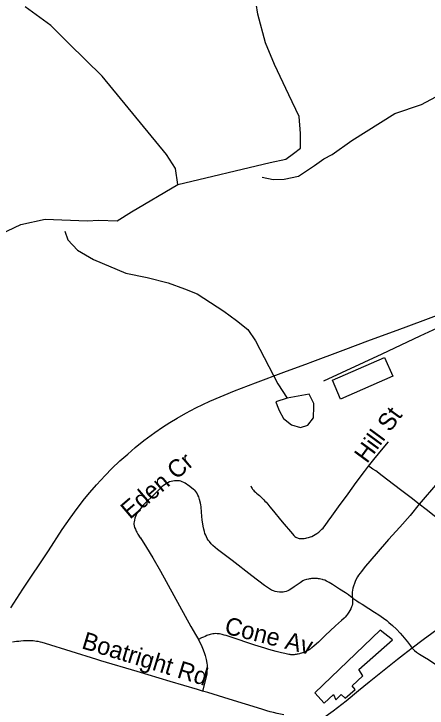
# Model space of a CAD drawing. Extents: x 1383679 to 1536984, y 460658 to 651027.
# Drawn here: x 1430469 to 1432722, y 488802 to 492583 of the extents above; entities that cross this region are included whole.
import ezdxf

# ---------------------------------------------------------------- set-up
doc = ezdxf.new("R2010")
doc.units = 0
for name, color, linetype in [('Exist Cultural Warehouse Building Footprint', 7, 'Continuous'), ('Exist Hydrographic Creek Single Shore', 7, 'Continuous'), ('Exist Hydrographic Misc Water Feature', 7, 'Continuous'), ('Exist Railroad Mainline', 7, 'Continuous'), ('Exist Railroad Spur', 7, 'Continuous'), ('Exist Road Non-System Type 51', 7, 'Continuous'), ('Exist Road Non-System Type 51 Label', 7, 'Continuous')]:
    doc.layers.add(name, color=color, linetype=linetype)

msp = doc.modelspace()

# ---------------------------------------------------------------- linework, layer by layer
at = {"layer": 'Exist Cultural Warehouse Building Footprint'}
for points in [[(1432489.4, 490712.1), (1432534.4, 490609.3), (1432250.4, 490484.9), (1432205.3, 490587.7), (1432489.4, 490712.1)], [(1432465.3, 489227), (1432110.3, 488885), (1432161, 488828.8), (1432211.7, 488875.7), (1432223.8, 488847.6), (1432252.8, 488875.7), (1432274.5, 488856.9), (1432330, 488903.8), (1432313.1, 488922.5), (1432371.1, 488978.7), (1432349.4, 489011.5), (1432532.9, 489173.2), (1432465.3, 489227)]]:
    msp.add_lwpolyline(points, dxfattribs=at)
at = {"layer": 'Exist Hydrographic Creek Single Shore'}
for points in [[(1431363.3, 491653.7), (1431867.1, 491773.5), (1431951.4, 491791.3), (1431993.6, 491822.4), (1432031.3, 491851.2), (1432031.3, 491931.1), (1432024.7, 492024.3), (1431968.2, 492141.9), (1431889.3, 492308.4), (1431841.6, 492426), (1431799.4, 492581.3), (1431762.8, 492816.6), (1431749.5, 492971.9), (1431774.4, 493174.4), (1431871.7, 493357.8), (1432018, 493546.7), (1432202.2, 493801.9), (1432237.7, 493963.9), (1432286.5, 494061.6), (1432324.2, 494168.1), (1432310.9, 494345.6), (1432318.7, 494667.4), (1432283.2, 494800.6), (1432128, 494953)], [(1431363.3, 491653.7), (1431350, 491740.3), (1431301, 491817.6), (1430950.6, 492244), (1430768.6, 492421.6), (1430670.9, 492519.2), (1430531.1, 492621.3)], [(1429661.1, 488410.2), (1429731.2, 488999.7), (1429702.2, 489233.3), (1429714.2, 489443.1), (1430018.5, 490728.3), (1430038.5, 490861.4), (1430062.9, 490923.6), (1430134.3, 490995.2), (1430204.6, 491104.1), (1430250.5, 491197), (1430311.4, 491309.7), (1430395.7, 491383), (1430506.7, 491436.2), (1430639.9, 491465.1), (1430868.4, 491456.2), (1430932.8, 491460.6), (1431032.7, 491456.2), (1431110.3, 491505), (1431363.3, 491653.7)]]:
    msp.add_lwpolyline(points, dxfattribs=at)
at = {"layer": 'Exist Hydrographic Misc Water Feature'}
for points in [[(1431822.6, 491694.3), (1431882.5, 491680.8), (1431942.6, 491683.7), (1432020.9, 491700.1), (1432108, 491756.7), (1432158.8, 491793.4), (1432205.2, 491817.1), (1432310.8, 491892.9), (1432545.8, 492040), (1432690.8, 492089.6), (1432848.5, 492172.6), (1433083.1, 492300), (1433113.3, 492307.5), (1433237.5, 492314.9), (1433352.6, 492366.8), (1433471, 492386.5), (1433557.9, 492430.7), (1433616.7, 492473.8), (1433675.3, 492498.9)], [(1430746.4, 491399.2), (1430763.5, 491352.9), (1430816.4, 491296), (1430903.5, 491245.9), (1431080.1, 491170.9), (1431195.8, 491148.1), (1431311.2, 491117.9), (1431398.7, 491086.6), (1431468.2, 491058.9), (1431614.4, 490964), (1431683.4, 490912.6), (1431744.5, 490863.8), (1431787.3, 490802.2), (1431833.5, 490711.8), (1431908.7, 490568.3), (1431959.3, 490491)], [(1431959.3, 490491), (1431896.8, 490470.1), (1431904.4, 490450.2), (1431915.9, 490423.8), (1431939.2, 490379.8), (1431982.5, 490344.5), (1432032.2, 490331.2), (1432072.5, 490342.6), (1432103.2, 490382.3), (1432104.5, 490444.6), (1432104.8, 490461.8), (1432079.8, 490512.4), (1431959.3, 490491)]]:
    msp.add_lwpolyline(points, dxfattribs=at)
at = {"layer": 'Exist Railroad Mainline'}
msp.add_lwpolyline([(1430451.7, 489348.5), (1430518.1, 489449.7), (1430657.3, 489659.4), (1430733.2, 489774.5), (1430775.8, 489837), (1430814.1, 489890), (1430854.1, 489941.3), (1430883.4, 489976.6), (1430919.1, 490018.3), (1430966.7, 490069.6), (1431003.4, 490106.9), (1431047.4, 490149), (1431089.8, 490185.8), (1431130.3, 490220.7), (1431178.3, 490259.2), (1431237.3, 490303.1), (1431279.3, 490332.1), (1431318.9, 490357.4), (1431359, 490381.6), (1431407.2, 490409.3), (1431460.9, 490437), (1431538, 490474.4), (1431671.2, 490529.9), (1431787.1, 490574.5), (1431941.2, 490631.6), (1432075, 490681.7), (1432083.6, 490684.9), (1432264.3, 490752), (1432414, 490807.1), (1432558.6, 490861.3), (1432699.7, 490913.9), (1432837.3, 490964.7)], dxfattribs=at)
at = {"layer": 'Exist Railroad Spur'}
msp.add_lwpolyline([(1433333.8, 491134.7), (1433229.3, 491091.6), (1432871.2, 490915), (1432682.9, 490828.4), (1432475, 490729.8), (1432156.3, 490582.2)], dxfattribs=at)
at = {"layer": 'Exist Road Non-System Type 51'}
for points in [[(1432403.2, 490119.3), (1432410.4, 490128.6), (1432431.3, 490155.3), (1432482, 490218), (1432510.7, 490252.4)], [(1432907, 490180), (1432901.9, 490173.5), (1432870, 490137.1), (1432830.9, 490092.5), (1432756.3, 490004.2), (1432699.7, 489937.5), (1432679.5, 489912.8)], [(1431760.8, 490013.3), (1431765.2, 490003.9), (1431768.4, 489998.6), (1431770.9, 489994.6), (1431775, 489989.3), (1431779.7, 489984.3), (1431785.6, 489978.7), (1431792, 489973.5), (1431800.6, 489966), (1431807.9, 489960), (1431812.9, 489955.4), (1431819.6, 489949.2), (1431827.1, 489942.1), (1431832.5, 489936.2), (1431837.9, 489929.8), (1431843.8, 489923), (1431853.3, 489912.4), (1431865.2, 489898.7), (1431875.9, 489885.9), (1431932.5, 489816.3), (1431988.3, 489750.7), (1431995.1, 489742.9), (1432000.6, 489737.4), (1432006.2, 489732.8), (1432009.9, 489730.4), (1432014.7, 489728.6), (1432019.1, 489727.3), (1432023.8, 489726.4), (1432031.1, 489725.5), (1432038.3, 489725.3), (1432046.2, 489726), (1432051.7, 489726.6), (1432061.5, 489728.2), (1432067, 489729.5), (1432075, 489731.1), (1432085.5, 489734.2), (1432094.3, 489737.6), (1432102.9, 489741.8), (1432112, 489747), (1432120.4, 489752.6), (1432131.2, 489760.9), (1432141.2, 489769.7), (1432148.2, 489776.4), (1432154.5, 489782.9), (1432159.6, 489788.4), (1432166.9, 489797.2), (1432183.4, 489819.7), (1432203.3, 489848), (1432239.5, 489898.2), (1432290.9, 489969.7), (1432335, 490030.5), (1432381.1, 490090.5), (1432403.2, 490119.3)], [(1432679.5, 489912.8), (1432635.6, 489946.5), (1432583.7, 489985.7), (1432538.8, 490020.5), (1432477.1, 490067.7), (1432442.3, 490093.5), (1432426.9, 490104.3), (1432412.2, 490113.6), (1432403.2, 490119.3)], [(1432314.9, 489401.9), (1432305.6, 489408.8), (1432292.8, 489418.2), (1432276.8, 489429.2), (1432245.1, 489449.9), (1432227.2, 489461), (1432206.2, 489474.9), (1432187.5, 489486.2), (1432173.5, 489493.9), (1432163.9, 489498.1), (1432156.2, 489501), (1432151.4, 489502.5), (1432142, 489505), (1432135.3, 489506.2), (1432130.3, 489506.9), (1432124.6, 489507.6), (1432115, 489508), (1432102.3, 489507.8), (1432092.3, 489507.2), (1432085.5, 489506.4), (1432079.9, 489505.5), (1432075, 489504.5), (1432063.7, 489502.5), (1432052.3, 489498.8), (1432044.8, 489495.4), (1432037, 489490.4), (1432029.3, 489485.1), (1432012.9, 489472.6), (1431997.2, 489461.7), (1431979.1, 489449.6), (1431969.9, 489444.1), (1431962.8, 489440.6), (1431954.3, 489437.7), (1431945, 489435.3), (1431937.3, 489434.2), (1431927.4, 489433.5), (1431917.1, 489433.6), (1431903.9, 489434.9), (1431893.3, 489436.6), (1431884.3, 489439.9), (1431873, 489445), (1431862.7, 489451.4), (1431847.2, 489461.7), (1431835.1, 489470.5), (1431765.6, 489523.3), (1431658.4, 489605.1), (1431579.1, 489665.9), (1431552.9, 489688.6), (1431545.1, 489696.6), (1431535, 489708.7), (1431528.6, 489717.2), (1431523.4, 489725.6), (1431518.5, 489735.1), (1431514.8, 489743.9), (1431511, 489752.7), (1431507.5, 489763.1), (1431504, 489776.1), (1431501.1, 489793.2), (1431499.6, 489805.3), (1431496.5, 489825.4), (1431492.4, 489869.7), (1431489.5, 489899), (1431488.4, 489908.7), (1431486.4, 489918.8), (1431481.7, 489938.2), (1431476.7, 489952.5), (1431472.9, 489962), (1431468.8, 489970.6), (1431466.3, 489975), (1431460.8, 489982.2), (1431454.9, 489988.4), (1431448.7, 489993.5), (1431429.3, 490008.5), (1431416.1, 490018.7), (1431410.4, 490022.6), (1431403.3, 490027), (1431395.7, 490031.1), (1431387.1, 490035.1), (1431378.9, 490038), (1431371.6, 490039.7), (1431364, 490040.8), (1431357.6, 490040.8), (1431350.9, 490040.2), (1431344.1, 490039.5), (1431335.1, 490038.4), (1431327.4, 490036.7), (1431317, 490033.6), (1431308.3, 490029.6), (1431301, 490025.6), (1431293.5, 490020.8), (1431284.9, 490014.4), (1431275.4, 490006.7), (1431262.7, 489995.4), (1431240.4, 489973.2), (1431219.1, 489951.4), (1431197.5, 489930.2), (1431185.4, 489918.3), (1431180.3, 489912.4), (1431174.6, 489906.5), (1431169.3, 489900.3)], [(1432679.5, 489912.8), (1432629.2, 489851.5), (1432572.6, 489787.2), (1432511.9, 489719.9), (1432444, 489642.9), (1432386.7, 489574.3), (1432363.2, 489545.1), (1432356.6, 489536.7), (1432348.8, 489526), (1432342.7, 489516.7), (1432336.1, 489505.1), (1432329.9, 489492.1), (1432325.4, 489481), (1432320.5, 489466.4), (1432317.1, 489454.7), (1432314.8, 489443.7), (1432313.7, 489433.7), (1432313.3, 489423.7), (1432313.9, 489412.3), (1432314.9, 489401.9)], [(1433170.9, 489523.4), (1433139.1, 489549.7), (1433069.9, 489606.1), (1432977.9, 489677.8), (1432848.3, 489780.4), (1432717, 489883.9), (1432679.5, 489912.8)], [(1431169.3, 489900.3), (1431147.9, 489875.2), (1431142.5, 489867.5), (1431138.5, 489860.7), (1431135.6, 489854.5), (1431131.9, 489846.1), (1431128.4, 489835.8), (1431126.2, 489825.9), (1431124.4, 489816.6), (1431123.7, 489809.8), (1431123.9, 489803.6), (1431125, 489795.2), (1431127.3, 489786.6), (1431131.4, 489775.8), (1431135.8, 489766.2), (1431138.7, 489760.6), (1431145.8, 489748.8), (1431158.1, 489729.7), (1431158.7, 489728.7), (1431191.8, 489676.6), (1431226.5, 489619.9), (1431268, 489547.8), (1431341.3, 489416.2), (1431434.5, 489246.9), (1431458.9, 489202.9), (1431475, 489175.3)], [(1433170.9, 489523.4), (1433131.7, 489494.3), (1433054.9, 489436.8), (1432984.9, 489386.3), (1432874.7, 489303.3), (1432794.1, 489242.5), (1432699.8, 489173.9), (1432640.6, 489128.7)], [(1432314.9, 489401.9), (1432315.6, 489393.8), (1432316.1, 489378.8), (1432315.2, 489370.4), (1432313, 489361.3), (1432310.2, 489353.2), (1432305.9, 489343.3), (1432300.9, 489333.6), (1432295.2, 489324.2), (1432288.6, 489314.2), (1432282.9, 489307.2), (1432275, 489298.1), (1432269, 489292), (1432255.6, 489278.8), (1432223.3, 489249.5), (1432167, 489197.4), (1432129, 489161.5), (1432106.7, 489141.8), (1432094, 489130.8), (1432090, 489127.6), (1432084.2, 489123.3), (1432078.8, 489120), (1432075, 489117.9), (1432075, 489117.9), (1432067.5, 489114.4), (1432060.5, 489110.8), (1432052.2, 489107.1), (1432047.7, 489105.2), (1432042.5, 489103), (1432036.5, 489101.1), (1432030.8, 489099.3), (1432025.8, 489097.9), (1432019.8, 489096.4), (1432014.3, 489095.1), (1432008.7, 489093.8), (1432003, 489093.2), (1431998, 489092.9), (1431992.2, 489092.7), (1431985.9, 489092.7), (1431979.6, 489093), (1431974.9, 489093.6), (1431967.6, 489094.8), (1431946.4, 489098.9), (1431928.3, 489102.9), (1431898.7, 489110.1), (1431878.3, 489115.2), (1431859.8, 489120.5), (1431837.2, 489127.6), (1431782.2, 489145.5), (1431647.9, 489191), (1431627, 489197.4), (1431616, 489200.2), (1431604.2, 489202.8), (1431596.6, 489204.5), (1431590.3, 489205.7), (1431583.3, 489206.6), (1431577, 489207.1), (1431569.5, 489207.5), (1431560.5, 489207.4), (1431553.3, 489206.6), (1431547.2, 489205.6), (1431539.7, 489203.4), (1431533, 489201.5), (1431527.1, 489199.4), (1431521.9, 489197.5), (1431511.6, 489192.9), (1431503.3, 489189.1), (1431492.4, 489184.2), (1431475, 489175.3)], [(1432314.9, 489401.9), (1432316.9, 489400.5), (1432338.6, 489386.1), (1432352.2, 489377.9), (1432368.4, 489368), (1432404.4, 489344.9), (1432435.9, 489324.5), (1432459.2, 489309.2), (1432471.7, 489300.3), (1432484.2, 489291.4), (1432501.6, 489278.4), (1432513.7, 489268.8), (1432533.7, 489252), (1432555, 489231.6), (1432574.8, 489210.7), (1432588.6, 489195.9), (1432597.4, 489185.5), (1432615.3, 489163.4), (1432630.7, 489141.7), (1432640.6, 489128.7)], [(1431498.1, 488895.1), (1431469.7, 488903.6), (1431322, 488947.7), (1431141.4, 489000.8), (1430943.7, 489059.2), (1430922.2, 489066), (1430642.4, 489153.6), (1430623.3, 489159.3), (1430613.5, 489161.7), (1430601, 489164.4), (1430592.2, 489165.7), (1430584, 489166.7), (1430574, 489167.6), (1430564.4, 489168.2), (1430556, 489168.5), (1430547.9, 489168.6), (1430540.7, 489168.5), (1430533.3, 489168.2), (1430521.7, 489167.6), (1430506.9, 489166.5), (1430495.8, 489165.5), (1430484.2, 489164.2), (1430472.5, 489162.4), (1430462.2, 489160.4)], [(1431475, 489175.3), (1431479.6, 489167.4), (1431490.1, 489146.6), (1431498.3, 489128.6), (1431506.5, 489105), (1431511.3, 489088.3), (1431517.9, 489066), (1431521, 489047), (1431522.2, 489036), (1431522.8, 489021.2), (1431522, 489007.3), (1431520.2, 488988.7), (1431517.4, 488971.9), (1431512.4, 488949.7), (1431498.1, 488895.1)], [(1432640.6, 489128.7), (1432593.4, 489092.6), (1432560.2, 489066), (1432405.9, 488942.5), (1432348.8, 488895.4), (1432280.3, 488839.8), (1432210.1, 488785.8), (1432146.2, 488739.5), (1432105.2, 488711.9)], [(1432640.6, 489128.7), (1432641.3, 489127.8), (1432645.5, 489123.6), (1432654, 489115.4), (1432664, 489107.6), (1432681.1, 489096.3), (1432707.8, 489079.2), (1432728.8, 489066), (1432764.5, 489043.6), (1432855.9, 488985), (1432882.7, 488967.9), (1432893.1, 488960.4), (1432902.2, 488953), (1432909.7, 488945.8), (1432916.9, 488937.7), (1432922.5, 488929.7), (1432971.6, 488861.3), (1433063.9, 488737)], [(1431941.6, 488766.1), (1431923, 488768.4), (1431905.1, 488772.1), (1431884.7, 488777.2), (1431866.4, 488782.3), (1431848.3, 488787.4), (1431821.5, 488795.5), (1431643.4, 488851.1), (1431526.5, 488886.6), (1431498.1, 488895.1)]]:
    msp.add_lwpolyline(points, dxfattribs=at)

# ---------------------------------------------------------------- texts
at = {"layer": 'Exist Road Non-System Type 51 Label'}
for s, rotation, p in [('Hill St', 53.6739, (1432394.2, 490130.4)), ('Eden Cr', 40.5345, (1431102.2, 489827)), ('Cone Av', 345.9645, (1431612.4, 489209.3)), ('Boatright Rd', 343.0488, (1430833.6, 489128.9))]:
    msp.add_text(s, height=95, rotation=rotation, dxfattribs=at).set_placement(p)

doc.saveas('drawing.dxf')
